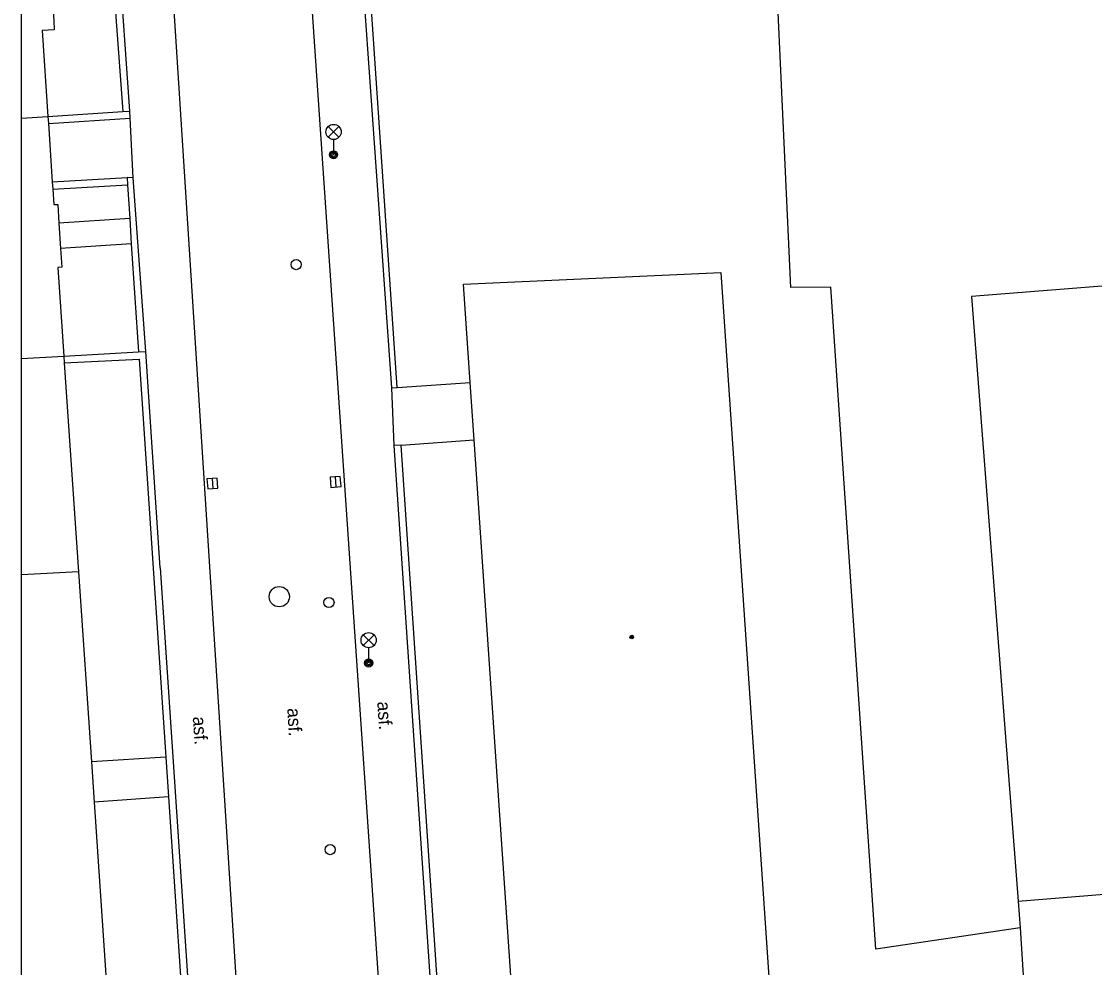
# Model space of a CAD drawing. Extents: x -596024 to -594475, y -1163820 to -1161957.
# Drawn here: x -596024.4 to -595971.5, y -1162076.4 to -1162029.7 of the extents above; entities that cross this region are included whole.
import ezdxf

# ---------------------------------------------------------------- set-up
doc = ezdxf.new("R2010")
doc.units = 0
for name, color, linetype in [('Level 10', 7, 'Continuous'), ('Level 11', 7, 'Continuous'), ('Level 27', 7, 'Continuous'), ('Level 28', 7, 'Continuous'), ('Level 33', 7, 'Continuous'), ('Level 39', 7, 'Continuous'), ('Level 40', 7, 'Continuous'), ('Level 5', 7, 'Continuous'), ('Level 7', 7, 'Continuous'), ('Level 8', 7, 'Continuous'), ('Vrstva 63', 7, 'Continuous')]:
    doc.layers.add(name, color=color, linetype=linetype)

msp = doc.modelspace()

# ---------------------------------------------------------------- linework, layer by layer
at = {"layer": 'Level 10'}
for points in [[(-596021.533, -1161956.88), (-596019.52, -1161988.41), (-596013.74, -1162078.43)], [(-596014.537, -1161956.88), (-596012.03, -1161996.13), (-596010.74, -1162019.65), (-596006.59, -1162080.3)]]:
    msp.add_lwpolyline(points, dxfattribs=at)
at = {"layer": 'Level 11'}
for points in [[(-595975.15, -1162074.45), (-595982.26, -1162075.51), (-595984.48, -1162042.85), (-595986.46, -1162042.87), (-595987.33, -1162023.94)], [(-596022.9, -1162037.66), (-596019.21, -1162037.45)], [(-596022.88, -1162038.01), (-596019.19, -1162037.8)], [(-596019.08, -1162039.47), (-596022.57, -1162039.7)], [(-596019, -1162040.72), (-596022.49, -1162040.95)], [(-595957.82, -1162041.75), (-595977.54, -1162043.32), (-595975.25, -1162073.14)], [(-596005.89, -1162047.8), (-596002.28, -1162047.55)], [(-596005.69, -1162050.64), (-596002.08, -1162050.39)], [(-596017.3, -1162066.03), (-596020.97, -1162066.27)], [(-596017.16, -1162068), (-596020.84, -1162068.25)], [(-595975.25, -1162073.14), (-595961.1, -1162071.99)], [(-595975.25, -1162073.14), (-595975.15, -1162074.45)], [(-595975.15, -1162074.45), (-595974, -1162092.58)]]:
    msp.add_lwpolyline(points, dxfattribs=at)
at = {"layer": 'Level 27'}
for p, q in [((-596015.017, -1162052.291), (-596014.983, -1162052.789)), ((-596008.937, -1162052.211), (-596008.903, -1162052.709))]:
    msp.add_line(p, q, dxfattribs=at)
for points in [[(-596015.267, -1162052.308), (-596015.232, -1162052.807), (-596014.733, -1162052.772), (-596014.768, -1162052.273)], [(-596009.187, -1162052.228), (-596009.152, -1162052.727), (-596008.653, -1162052.692), (-596008.688, -1162052.193)]]:
    msp.add_lwpolyline(points, close=True, dxfattribs=at)
msp.add_circle((-596011.7, -1162058.12), 0.5, dxfattribs=at)
at = {"layer": 'Level 28'}
for centre in [(-596010.87, -1162041.74), (-596009.25, -1162058.41), (-596009.19, -1162070.6)]:
    msp.add_circle(centre, 0.25, dxfattribs=at)
at = {"layer": 'Level 33'}
for p, q in [((-596009.285, -1162035.46), (-596008.755, -1162034.93)), ((-596009.285, -1162034.93), (-596008.755, -1162035.46)), ((-596009.02, -1162035.57), (-596009.02, -1162036.32)), ((-596007.555, -1162060.53), (-596007.025, -1162060)), ((-596007.555, -1162060), (-596007.025, -1162060.53)), ((-596007.29, -1162060.64), (-596007.29, -1162061.39))]:
    msp.add_line(p, q, dxfattribs=at)
for centre, radius in [((-596009.02, -1162035.195), 0.375), ((-596009.02, -1162036.32), 0.2), ((-596009.02, -1162036.32), 0.145), ((-596009.02, -1162036.32), 0.0876), ((-596007.29, -1162060.265), 0.375), ((-596007.29, -1162061.39), 0.2), ((-596007.29, -1162061.39), 0.145), ((-596007.29, -1162061.39), 0.0876)]:
    msp.add_circle(centre, radius, dxfattribs=at)
at = {"layer": 'Level 39'}
for radius in [0.09, 0.0398]:
    msp.add_circle((-595994.31, -1162060.11), radius, dxfattribs=at)
at = {"layer": 'Level 5'}
for p, q in [((-596024.42, -1162034.513), (-596023.12, -1162034.44)), ((-596024.42, -1162046.376), (-596022.33, -1162046.25)), ((-596021.61, -1162056.9), (-596024.42, -1162057.048))]:
    msp.add_line(p, q, dxfattribs=at)
for points in [[(-596022.98, -1162027.39), (-596022.83, -1162029.69), (-596022.8, -1162030.16)], [(-596022.8, -1162030.16), (-596023.4, -1162030.19)], [(-596023.4, -1162030.19), (-596023.12, -1162034.44)], [(-596023.12, -1162034.44), (-596023.09, -1162034.78)], [(-596023.09, -1162034.78), (-596022.9, -1162037.66)], [(-596022.9, -1162037.66), (-596022.88, -1162038.01)], [(-596022.88, -1162038.01), (-596022.83, -1162038.78)], [(-596022.83, -1162038.78), (-596022.63, -1162038.77)], [(-596022.63, -1162038.77), (-596022.57, -1162039.7), (-596022.49, -1162040.95), (-596022.43, -1162041.86)], [(-596022.43, -1162041.86), (-596022.63, -1162041.88)], [(-596022.63, -1162041.88), (-596022.33, -1162046.25)], [(-596002.61, -1162042.7), (-595989.92, -1162042.13)], [(-595989.92, -1162042.13), (-595986.93, -1162085.81)], [(-595999.6, -1162086.68), (-596002.08, -1162050.39), (-596002.28, -1162047.55), (-596002.61, -1162042.7)], [(-596022.33, -1162046.25), (-596022.31, -1162046.59)], [(-596022.31, -1162046.59), (-596021.61, -1162056.9)], [(-596021.61, -1162056.9), (-596020.97, -1162066.27), (-596020.84, -1162068.25), (-596020.21, -1162077.52)]]:
    msp.add_lwpolyline(points, dxfattribs=at)
at = {"layer": 'Level 7'}
for points in [[(-596007.77, -1162025.05), (-596006.16, -1162047.82)], [(-596006.16, -1162047.82), (-596005.89, -1162047.8), (-596007.43, -1162025.03)], [(-596019.07, -1162034.17), (-596019.62, -1162026.43)], [(-596019.95, -1162026.81), (-596019.92, -1162027.21), (-596019.76, -1162029.51), (-596019.42, -1162034.19)], [(-596023.12, -1162034.44), (-596019.42, -1162034.19)], [(-596023.09, -1162034.78), (-596019.05, -1162034.51)], [(-596019.42, -1162034.19), (-596019.07, -1162034.17)], [(-596019.05, -1162034.51), (-596019.07, -1162034.17)], [(-596019.21, -1162037.45), (-596019.19, -1162037.8)], [(-596018.91, -1162037.46), (-596019.21, -1162037.45)], [(-596019.19, -1162037.8), (-596019.08, -1162039.47), (-596019, -1162040.72), (-596018.64, -1162046.05)], [(-596018.29, -1162046.03), (-596018.91, -1162037.46)], [(-596022.33, -1162046.25), (-596018.64, -1162046.05)], [(-596018.64, -1162046.05), (-596018.29, -1162046.03)], [(-596017.57, -1162056.69), (-596018.29, -1162046.03)], [(-596022.31, -1162046.59), (-596018.61, -1162046.41)], [(-596018.61, -1162046.41), (-596017.92, -1162056.71), (-596017.3, -1162066.03), (-596017.16, -1162068), (-596016.54, -1162077.34), (-596016.38, -1162079.68), (-596016.24, -1162081.78), (-596015.61, -1162091.1)], [(-596003.05, -1162089.7), (-596005.69, -1162050.64), (-596006.04, -1162050.66)], [(-596006.04, -1162050.66), (-596003.42, -1162089.46), (-596003.4, -1162089.72)], [(-596017.57, -1162056.69), (-596016.19, -1162077.32)]]:
    msp.add_lwpolyline(points, dxfattribs=at)
at = {"layer": 'Level 8'}
for points in [[(-596018.91, -1162037.46), (-596019.05, -1162034.51)], [(-596006.16, -1162047.82), (-596006.04, -1162050.66)]]:
    msp.add_lwpolyline(points, dxfattribs=at)
at = {"layer": 'Vrstva 63'}
msp.add_lwpolyline([(-594475.47, -1163820.23), (-596024.42, -1163820.23), (-596024.42, -1161956.88), (-594475.47, -1161956.88)], close=True, dxfattribs=at)

# ---------------------------------------------------------------- texts
at = {"layer": 'Level 40'}
for rotation, p in [(273.6008, (-596011.31, -1162063.63)), (274, (-596006.87, -1162063.31)), (274, (-596015.97, -1162064.05))]:
    msp.add_text('asf.', height=0.65, rotation=rotation, dxfattribs=at).set_placement(p)

doc.saveas('drawing.dxf')
